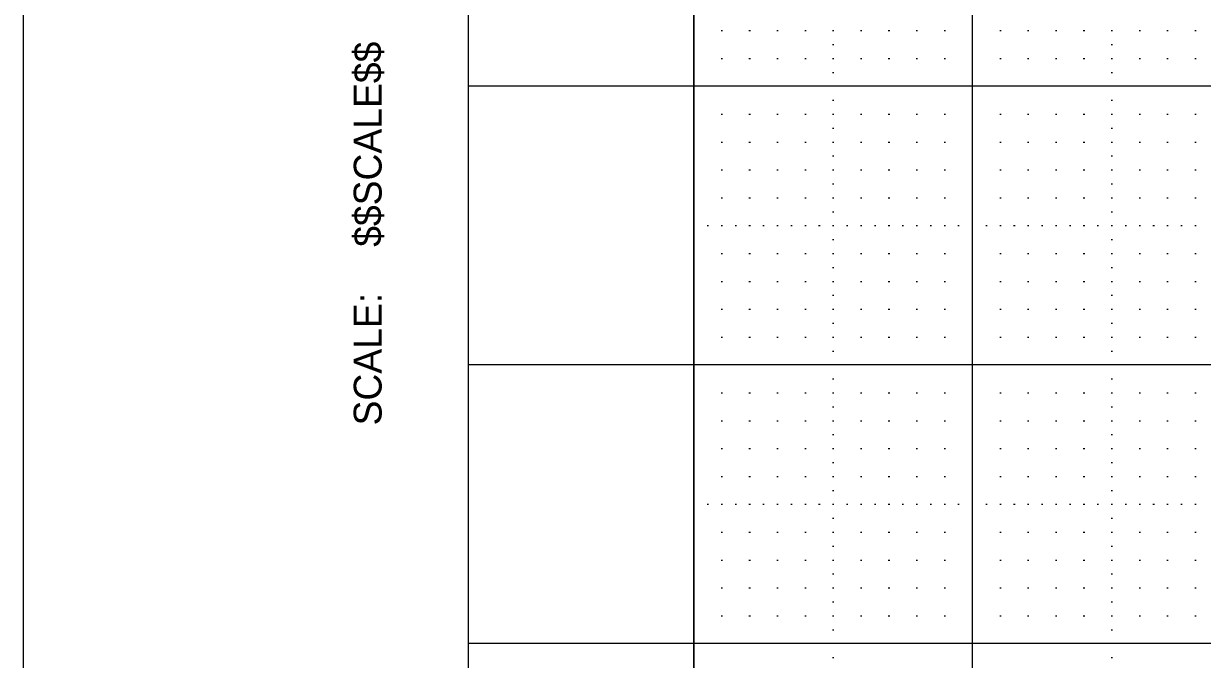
# Model space of a CAD drawing. Extents: x -1.6 to 32.4, y -1.9 to 21.6.
# Drawn here: x -1.598 to 2.633, y 2.488 to 4.77 of the extents above; entities that cross this region are included whole.
import ezdxf

# ---------------------------------------------------------------- set-up
doc = ezdxf.new("R2010")
doc.units = 0
for name, color, linetype in [('Level 1', 7, 'Continuous'), ('Level 4', 7, 'Continuous'), ('Level 5', 7, 'Continuous'), ('Level 61', 7, 'Continuous'), ('Level 63', 7, 'Continuous')]:
    doc.layers.add(name, color=color, linetype=linetype)

msp = doc.modelspace()

# ---------------------------------------------------------------- linework, layer by layer
at = {"layer": 'Level 1'}
msp.add_line((-0.001, -0.001), (-0.001, 20.545), dxfattribs=at)
at = {"layer": 'Level 4'}
for p, q in [((0.808, 0.545), (0.808, 20.545)), ((1.808, 0.545), (1.808, 20.545)), ((31.617, 4.545), (-0.001, 4.545)), ((31.617, 3.545), (-0.001, 3.545)), ((31.617, 2.545), (-0.001, 2.545))]:
    msp.add_line(p, q, dxfattribs=at)
at = {"layer": 'Level 5'}
for p, q in [((0.9055, 4.745), (0.9105, 4.745)), ((1.0055, 4.745), (1.0105, 4.745)), ((1.1055, 4.745), (1.1105, 4.745)), ((1.2055, 4.745), (1.2105, 4.745)), ((1.3055, 4.745), (1.3105, 4.745)), ((1.4055, 4.745), (1.4105, 4.745)), ((1.5055, 4.745), (1.5105, 4.745)), ((1.6055, 4.745), (1.6105, 4.745)), ((1.7055, 4.745), (1.7105, 4.745)), ((1.9055, 4.745), (1.9105, 4.745)), ((2.0055, 4.745), (2.0105, 4.745)), ((2.1055, 4.745), (2.1105, 4.745)), ((2.2055, 4.745), (2.2105, 4.745)), ((2.3055, 4.745), (2.3105, 4.745)), ((2.4055, 4.745), (2.4105, 4.745)), ((2.5055, 4.745), (2.5105, 4.745)), ((2.6055, 4.745), (2.6105, 4.745)), ((1.3055, 4.695), (1.3105, 4.695)), ((2.3055, 4.695), (2.3105, 4.695)), ((0.9055, 4.645), (0.9105, 4.645)), ((1.0055, 4.645), (1.0105, 4.645)), ((1.1055, 4.645), (1.1105, 4.645)), ((1.2055, 4.645), (1.2105, 4.645)), ((1.3055, 4.645), (1.3105, 4.645)), ((1.4055, 4.645), (1.4105, 4.645)), ((1.5055, 4.645), (1.5105, 4.645)), ((1.6055, 4.645), (1.6105, 4.645)), ((1.7055, 4.645), (1.7105, 4.645)), ((1.9055, 4.645), (1.9105, 4.645)), ((2.0055, 4.645), (2.0105, 4.645)), ((2.1055, 4.645), (2.1105, 4.645)), ((2.2055, 4.645), (2.2105, 4.645)), ((2.3055, 4.645), (2.3105, 4.645)), ((2.4055, 4.645), (2.4105, 4.645)), ((2.5055, 4.645), (2.5105, 4.645)), ((2.6055, 4.645), (2.6105, 4.645)), ((1.3055, 4.595), (1.3105, 4.595)), ((2.3055, 4.595), (2.3105, 4.595)), ((1.3055, 4.495), (1.3105, 4.495)), ((2.3055, 4.495), (2.3105, 4.495)), ((0.9055, 4.445), (0.9105, 4.445)), ((1.0055, 4.445), (1.0105, 4.445)), ((1.1055, 4.445), (1.1105, 4.445)), ((1.2055, 4.445), (1.2105, 4.445)), ((1.3055, 4.445), (1.3105, 4.445)), ((1.4055, 4.445), (1.4105, 4.445)), ((1.5055, 4.445), (1.5105, 4.445)), ((1.6055, 4.445), (1.6105, 4.445)), ((1.7055, 4.445), (1.7105, 4.445)), ((1.9055, 4.445), (1.9105, 4.445)), ((2.0055, 4.445), (2.0105, 4.445)), ((2.1055, 4.445), (2.1105, 4.445)), ((2.2055, 4.445), (2.2105, 4.445)), ((2.3055, 4.445), (2.3105, 4.445)), ((2.4055, 4.445), (2.4105, 4.445)), ((2.5055, 4.445), (2.5105, 4.445)), ((2.6055, 4.445), (2.6105, 4.445)), ((1.3055, 4.395), (1.3105, 4.395)), ((2.3055, 4.395), (2.3105, 4.395)), ((0.9055, 4.345), (0.9105, 4.345)), ((1.0055, 4.345), (1.0105, 4.345)), ((1.1055, 4.345), (1.1105, 4.345)), ((1.2055, 4.345), (1.2105, 4.345)), ((1.3055, 4.345), (1.3105, 4.345)), ((1.4055, 4.345), (1.4105, 4.345)), ((1.5055, 4.345), (1.5105, 4.345)), ((1.6055, 4.345), (1.6105, 4.345)), ((1.7055, 4.345), (1.7105, 4.345)), ((1.9055, 4.345), (1.9105, 4.345)), ((2.0055, 4.345), (2.0105, 4.345)), ((2.1055, 4.345), (2.1105, 4.345)), ((2.2055, 4.345), (2.2105, 4.345)), ((2.3055, 4.345), (2.3105, 4.345)), ((2.4055, 4.345), (2.4105, 4.345)), ((2.5055, 4.345), (2.5105, 4.345)), ((2.6055, 4.345), (2.6105, 4.345)), ((1.3055, 4.295), (1.3105, 4.295)), ((2.3055, 4.295), (2.3105, 4.295)), ((0.9055, 4.245), (0.9105, 4.245)), ((1.0055, 4.245), (1.0105, 4.245)), ((1.1055, 4.245), (1.1105, 4.245)), ((1.2055, 4.245), (1.2105, 4.245)), ((1.3055, 4.245), (1.3105, 4.245)), ((1.4055, 4.245), (1.4105, 4.245)), ((1.5055, 4.245), (1.5105, 4.245)), ((1.6055, 4.245), (1.6105, 4.245)), ((1.7055, 4.245), (1.7105, 4.245)), ((1.9055, 4.245), (1.9105, 4.245)), ((2.0055, 4.245), (2.0105, 4.245)), ((2.1055, 4.245), (2.1105, 4.245)), ((2.2055, 4.245), (2.2105, 4.245)), ((2.3055, 4.245), (2.3105, 4.245)), ((2.4055, 4.245), (2.4105, 4.245)), ((2.5055, 4.245), (2.5105, 4.245)), ((2.6055, 4.245), (2.6105, 4.245)), ((1.3055, 4.195), (1.3105, 4.195)), ((2.3055, 4.195), (2.3105, 4.195)), ((0.9055, 4.145), (0.9105, 4.145)), ((1.0055, 4.145), (1.0105, 4.145)), ((1.1055, 4.145), (1.1105, 4.145)), ((1.2055, 4.145), (1.2105, 4.145)), ((1.3055, 4.145), (1.3105, 4.145)), ((1.4055, 4.145), (1.4105, 4.145)), ((1.5055, 4.145), (1.5105, 4.145)), ((1.6055, 4.145), (1.6105, 4.145)), ((1.7055, 4.145), (1.7105, 4.145)), ((1.9055, 4.145), (1.9105, 4.145)), ((2.0055, 4.145), (2.0105, 4.145)), ((2.1055, 4.145), (2.1105, 4.145)), ((2.2055, 4.145), (2.2105, 4.145)), ((2.3055, 4.145), (2.3105, 4.145)), ((2.4055, 4.145), (2.4105, 4.145)), ((2.5055, 4.145), (2.5105, 4.145)), ((2.6055, 4.145), (2.6105, 4.145)), ((1.3055, 4.095), (1.3105, 4.095)), ((2.3055, 4.095), (2.3105, 4.095)), ((0.8555, 4.045), (0.8605, 4.045)), ((0.9055, 4.045), (0.9105, 4.045)), ((0.9555, 4.045), (0.9605, 4.045)), ((1.0055, 4.045), (1.0105, 4.045)), ((1.0555, 4.045), (1.0605, 4.045)), ((1.1055, 4.045), (1.1105, 4.045)), ((1.1555, 4.045), (1.1605, 4.045)), ((1.2055, 4.045), (1.2105, 4.045)), ((1.2555, 4.045), (1.2605, 4.045)), ((1.3055, 4.045), (1.3105, 4.045)), ((1.3555, 4.045), (1.3605, 4.045)), ((1.4055, 4.045), (1.4105, 4.045)), ((1.4555, 4.045), (1.4605, 4.045)), ((1.5055, 4.045), (1.5105, 4.045)), ((1.5555, 4.045), (1.5605, 4.045)), ((1.6055, 4.045), (1.6105, 4.045)), ((1.6555, 4.045), (1.6605, 4.045)), ((1.7055, 4.045), (1.7105, 4.045)), ((1.7555, 4.045), (1.7605, 4.045)), ((1.8555, 4.045), (1.8605, 4.045)), ((1.9055, 4.045), (1.9105, 4.045)), ((1.9555, 4.045), (1.9605, 4.045)), ((2.0055, 4.045), (2.0105, 4.045)), ((2.0555, 4.045), (2.0605, 4.045)), ((2.1055, 4.045), (2.1105, 4.045)), ((2.1555, 4.045), (2.1605, 4.045)), ((2.2055, 4.045), (2.2105, 4.045)), ((2.2555, 4.045), (2.2605, 4.045)), ((2.3055, 4.045), (2.3105, 4.045)), ((2.3555, 4.045), (2.3605, 4.045)), ((2.4055, 4.045), (2.4105, 4.045)), ((2.4555, 4.045), (2.4605, 4.045)), ((2.5055, 4.045), (2.5105, 4.045)), ((2.5555, 4.045), (2.5605, 4.045)), ((2.6055, 4.045), (2.6105, 4.045)), ((1.3055, 3.995), (1.3105, 3.995)), ((2.3055, 3.995), (2.3105, 3.995)), ((0.9055, 3.945), (0.9105, 3.945)), ((1.0055, 3.945), (1.0105, 3.945)), ((1.1055, 3.945), (1.1105, 3.945)), ((1.2055, 3.945), (1.2105, 3.945)), ((1.3055, 3.945), (1.3105, 3.945)), ((1.4055, 3.945), (1.4105, 3.945)), ((1.5055, 3.945), (1.5105, 3.945)), ((1.6055, 3.945), (1.6105, 3.945)), ((1.7055, 3.945), (1.7105, 3.945)), ((1.9055, 3.945), (1.9105, 3.945)), ((2.0055, 3.945), (2.0105, 3.945)), ((2.1055, 3.945), (2.1105, 3.945)), ((2.2055, 3.945), (2.2105, 3.945)), ((2.3055, 3.945), (2.3105, 3.945)), ((2.4055, 3.945), (2.4105, 3.945)), ((2.5055, 3.945), (2.5105, 3.945)), ((2.6055, 3.945), (2.6105, 3.945)), ((1.3055, 3.895), (1.3105, 3.895)), ((2.3055, 3.895), (2.3105, 3.895)), ((0.9055, 3.845), (0.9105, 3.845)), ((1.0055, 3.845), (1.0105, 3.845)), ((1.1055, 3.845), (1.1105, 3.845)), ((1.2055, 3.845), (1.2105, 3.845)), ((1.3055, 3.845), (1.3105, 3.845)), ((1.4055, 3.845), (1.4105, 3.845)), ((1.5055, 3.845), (1.5105, 3.845)), ((1.6055, 3.845), (1.6105, 3.845)), ((1.7055, 3.845), (1.7105, 3.845)), ((1.9055, 3.845), (1.9105, 3.845)), ((2.0055, 3.845), (2.0105, 3.845)), ((2.1055, 3.845), (2.1105, 3.845)), ((2.2055, 3.845), (2.2105, 3.845)), ((2.3055, 3.845), (2.3105, 3.845)), ((2.4055, 3.845), (2.4105, 3.845)), ((2.5055, 3.845), (2.5105, 3.845)), ((2.6055, 3.845), (2.6105, 3.845)), ((1.3055, 3.795), (1.3105, 3.795)), ((2.3055, 3.795), (2.3105, 3.795)), ((0.9055, 3.745), (0.9105, 3.745)), ((1.0055, 3.745), (1.0105, 3.745)), ((1.1055, 3.745), (1.1105, 3.745)), ((1.2055, 3.745), (1.2105, 3.745)), ((1.3055, 3.745), (1.3105, 3.745)), ((1.4055, 3.745), (1.4105, 3.745)), ((1.5055, 3.745), (1.5105, 3.745)), ((1.6055, 3.745), (1.6105, 3.745)), ((1.7055, 3.745), (1.7105, 3.745)), ((1.9055, 3.745), (1.9105, 3.745)), ((2.0055, 3.745), (2.0105, 3.745)), ((2.1055, 3.745), (2.1105, 3.745)), ((2.2055, 3.745), (2.2105, 3.745)), ((2.3055, 3.745), (2.3105, 3.745)), ((2.4055, 3.745), (2.4105, 3.745)), ((2.5055, 3.745), (2.5105, 3.745)), ((2.6055, 3.745), (2.6105, 3.745)), ((1.3055, 3.695), (1.3105, 3.695)), ((2.3055, 3.695), (2.3105, 3.695)), ((0.9055, 3.645), (0.9105, 3.645)), ((1.0055, 3.645), (1.0105, 3.645)), ((1.1055, 3.645), (1.1105, 3.645)), ((1.2055, 3.645), (1.2105, 3.645)), ((1.3055, 3.645), (1.3105, 3.645)), ((1.4055, 3.645), (1.4105, 3.645)), ((1.5055, 3.645), (1.5105, 3.645)), ((1.6055, 3.645), (1.6105, 3.645)), ((1.7055, 3.645), (1.7105, 3.645)), ((1.9055, 3.645), (1.9105, 3.645)), ((2.0055, 3.645), (2.0105, 3.645)), ((2.1055, 3.645), (2.1105, 3.645)), ((2.2055, 3.645), (2.2105, 3.645)), ((2.3055, 3.645), (2.3105, 3.645)), ((2.4055, 3.645), (2.4105, 3.645)), ((2.5055, 3.645), (2.5105, 3.645)), ((2.6055, 3.645), (2.6105, 3.645)), ((1.3055, 3.595), (1.3105, 3.595)), ((2.3055, 3.595), (2.3105, 3.595)), ((1.3055, 3.495), (1.3105, 3.495)), ((2.3055, 3.495), (2.3105, 3.495)), ((0.9055, 3.445), (0.9105, 3.445)), ((1.0055, 3.445), (1.0105, 3.445)), ((1.1055, 3.445), (1.1105, 3.445)), ((1.2055, 3.445), (1.2105, 3.445)), ((1.3055, 3.445), (1.3105, 3.445)), ((1.4055, 3.445), (1.4105, 3.445)), ((1.5055, 3.445), (1.5105, 3.445)), ((1.6055, 3.445), (1.6105, 3.445)), ((1.7055, 3.445), (1.7105, 3.445)), ((1.9055, 3.445), (1.9105, 3.445)), ((2.0055, 3.445), (2.0105, 3.445)), ((2.1055, 3.445), (2.1105, 3.445)), ((2.2055, 3.445), (2.2105, 3.445)), ((2.3055, 3.445), (2.3105, 3.445)), ((2.4055, 3.445), (2.4105, 3.445)), ((2.5055, 3.445), (2.5105, 3.445)), ((2.6055, 3.445), (2.6105, 3.445)), ((1.3055, 3.395), (1.3105, 3.395)), ((2.3055, 3.395), (2.3105, 3.395)), ((0.9055, 3.345), (0.9105, 3.345)), ((1.0055, 3.345), (1.0105, 3.345)), ((1.1055, 3.345), (1.1105, 3.345)), ((1.2055, 3.345), (1.2105, 3.345)), ((1.3055, 3.345), (1.3105, 3.345)), ((1.4055, 3.345), (1.4105, 3.345)), ((1.5055, 3.345), (1.5105, 3.345)), ((1.6055, 3.345), (1.6105, 3.345)), ((1.7055, 3.345), (1.7105, 3.345)), ((1.9055, 3.345), (1.9105, 3.345)), ((2.0055, 3.345), (2.0105, 3.345)), ((2.1055, 3.345), (2.1105, 3.345)), ((2.2055, 3.345), (2.2105, 3.345)), ((2.3055, 3.345), (2.3105, 3.345)), ((2.4055, 3.345), (2.4105, 3.345)), ((2.5055, 3.345), (2.5105, 3.345)), ((2.6055, 3.345), (2.6105, 3.345)), ((1.3055, 3.295), (1.3105, 3.295)), ((2.3055, 3.295), (2.3105, 3.295)), ((0.9055, 3.245), (0.9105, 3.245)), ((1.0055, 3.245), (1.0105, 3.245)), ((1.1055, 3.245), (1.1105, 3.245)), ((1.2055, 3.245), (1.2105, 3.245)), ((1.3055, 3.245), (1.3105, 3.245)), ((1.4055, 3.245), (1.4105, 3.245)), ((1.5055, 3.245), (1.5105, 3.245)), ((1.6055, 3.245), (1.6105, 3.245)), ((1.7055, 3.245), (1.7105, 3.245)), ((1.9055, 3.245), (1.9105, 3.245)), ((2.0055, 3.245), (2.0105, 3.245)), ((2.1055, 3.245), (2.1105, 3.245)), ((2.2055, 3.245), (2.2105, 3.245)), ((2.3055, 3.245), (2.3105, 3.245)), ((2.4055, 3.245), (2.4105, 3.245)), ((2.5055, 3.245), (2.5105, 3.245)), ((2.6055, 3.245), (2.6105, 3.245)), ((1.3055, 3.195), (1.3105, 3.195)), ((2.3055, 3.195), (2.3105, 3.195)), ((0.9055, 3.145), (0.9105, 3.145)), ((1.0055, 3.145), (1.0105, 3.145)), ((1.1055, 3.145), (1.1105, 3.145)), ((1.2055, 3.145), (1.2105, 3.145)), ((1.3055, 3.145), (1.3105, 3.145)), ((1.4055, 3.145), (1.4105, 3.145)), ((1.5055, 3.145), (1.5105, 3.145)), ((1.6055, 3.145), (1.6105, 3.145)), ((1.7055, 3.145), (1.7105, 3.145)), ((1.9055, 3.145), (1.9105, 3.145)), ((2.0055, 3.145), (2.0105, 3.145)), ((2.1055, 3.145), (2.1105, 3.145)), ((2.2055, 3.145), (2.2105, 3.145)), ((2.3055, 3.145), (2.3105, 3.145)), ((2.4055, 3.145), (2.4105, 3.145)), ((2.5055, 3.145), (2.5105, 3.145)), ((2.6055, 3.145), (2.6105, 3.145)), ((1.3055, 3.095), (1.3105, 3.095)), ((2.3055, 3.095), (2.3105, 3.095)), ((0.8555, 3.045), (0.8605, 3.045)), ((0.9055, 3.045), (0.9105, 3.045)), ((0.9555, 3.045), (0.9605, 3.045)), ((1.0055, 3.045), (1.0105, 3.045)), ((1.0555, 3.045), (1.0605, 3.045)), ((1.1055, 3.045), (1.1105, 3.045)), ((1.1555, 3.045), (1.1605, 3.045)), ((1.2055, 3.045), (1.2105, 3.045)), ((1.2555, 3.045), (1.2605, 3.045)), ((1.3055, 3.045), (1.3105, 3.045)), ((1.3555, 3.045), (1.3605, 3.045)), ((1.4055, 3.045), (1.4105, 3.045)), ((1.4555, 3.045), (1.4605, 3.045)), ((1.5055, 3.045), (1.5105, 3.045)), ((1.5555, 3.045), (1.5605, 3.045)), ((1.6055, 3.045), (1.6105, 3.045)), ((1.6555, 3.045), (1.6605, 3.045)), ((1.7055, 3.045), (1.7105, 3.045)), ((1.7555, 3.045), (1.7605, 3.045)), ((1.8555, 3.045), (1.8605, 3.045)), ((1.9055, 3.045), (1.9105, 3.045)), ((1.9555, 3.045), (1.9605, 3.045)), ((2.0055, 3.045), (2.0105, 3.045)), ((2.0555, 3.045), (2.0605, 3.045)), ((2.1055, 3.045), (2.1105, 3.045)), ((2.1555, 3.045), (2.1605, 3.045)), ((2.2055, 3.045), (2.2105, 3.045)), ((2.2555, 3.045), (2.2605, 3.045)), ((2.3055, 3.045), (2.3105, 3.045)), ((2.3555, 3.045), (2.3605, 3.045)), ((2.4055, 3.045), (2.4105, 3.045)), ((2.4555, 3.045), (2.4605, 3.045)), ((2.5055, 3.045), (2.5105, 3.045)), ((2.5555, 3.045), (2.5605, 3.045)), ((2.6055, 3.045), (2.6105, 3.045)), ((1.3055, 2.995), (1.3105, 2.995)), ((2.3055, 2.995), (2.3105, 2.995)), ((0.9055, 2.945), (0.9105, 2.945)), ((1.0055, 2.945), (1.0105, 2.945)), ((1.1055, 2.945), (1.1105, 2.945)), ((1.2055, 2.945), (1.2105, 2.945)), ((1.3055, 2.945), (1.3105, 2.945)), ((1.4055, 2.945), (1.4105, 2.945)), ((1.5055, 2.945), (1.5105, 2.945)), ((1.6055, 2.945), (1.6105, 2.945)), ((1.7055, 2.945), (1.7105, 2.945)), ((1.9055, 2.945), (1.9105, 2.945)), ((2.0055, 2.945), (2.0105, 2.945)), ((2.1055, 2.945), (2.1105, 2.945)), ((2.2055, 2.945), (2.2105, 2.945)), ((2.3055, 2.945), (2.3105, 2.945)), ((2.4055, 2.945), (2.4105, 2.945)), ((2.5055, 2.945), (2.5105, 2.945)), ((2.6055, 2.945), (2.6105, 2.945)), ((1.3055, 2.895), (1.3105, 2.895)), ((2.3055, 2.895), (2.3105, 2.895)), ((0.9055, 2.845), (0.9105, 2.845)), ((1.0055, 2.845), (1.0105, 2.845)), ((1.1055, 2.845), (1.1105, 2.845)), ((1.2055, 2.845), (1.2105, 2.845)), ((1.3055, 2.845), (1.3105, 2.845)), ((1.4055, 2.845), (1.4105, 2.845)), ((1.5055, 2.845), (1.5105, 2.845)), ((1.6055, 2.845), (1.6105, 2.845)), ((1.7055, 2.845), (1.7105, 2.845)), ((1.9055, 2.845), (1.9105, 2.845)), ((2.0055, 2.845), (2.0105, 2.845)), ((2.1055, 2.845), (2.1105, 2.845)), ((2.2055, 2.845), (2.2105, 2.845)), ((2.3055, 2.845), (2.3105, 2.845)), ((2.4055, 2.845), (2.4105, 2.845)), ((2.5055, 2.845), (2.5105, 2.845)), ((2.6055, 2.845), (2.6105, 2.845)), ((1.3055, 2.795), (1.3105, 2.795)), ((2.3055, 2.795), (2.3105, 2.795)), ((0.9055, 2.745), (0.9105, 2.745)), ((1.0055, 2.745), (1.0105, 2.745)), ((1.1055, 2.745), (1.1105, 2.745)), ((1.2055, 2.745), (1.2105, 2.745)), ((1.3055, 2.745), (1.3105, 2.745)), ((1.4055, 2.745), (1.4105, 2.745)), ((1.5055, 2.745), (1.5105, 2.745)), ((1.6055, 2.745), (1.6105, 2.745)), ((1.7055, 2.745), (1.7105, 2.745)), ((1.9055, 2.745), (1.9105, 2.745)), ((2.0055, 2.745), (2.0105, 2.745)), ((2.1055, 2.745), (2.1105, 2.745)), ((2.2055, 2.745), (2.2105, 2.745)), ((2.3055, 2.745), (2.3105, 2.745)), ((2.4055, 2.745), (2.4105, 2.745)), ((2.5055, 2.745), (2.5105, 2.745)), ((2.6055, 2.745), (2.6105, 2.745)), ((1.3055, 2.695), (1.3105, 2.695)), ((2.3055, 2.695), (2.3105, 2.695)), ((0.9055, 2.645), (0.9105, 2.645)), ((1.0055, 2.645), (1.0105, 2.645)), ((1.1055, 2.645), (1.1105, 2.645)), ((1.2055, 2.645), (1.2105, 2.645)), ((1.3055, 2.645), (1.3105, 2.645)), ((1.4055, 2.645), (1.4105, 2.645)), ((1.5055, 2.645), (1.5105, 2.645)), ((1.6055, 2.645), (1.6105, 2.645)), ((1.7055, 2.645), (1.7105, 2.645)), ((1.9055, 2.645), (1.9105, 2.645)), ((2.0055, 2.645), (2.0105, 2.645)), ((2.1055, 2.645), (2.1105, 2.645)), ((2.2055, 2.645), (2.2105, 2.645)), ((2.3055, 2.645), (2.3105, 2.645)), ((2.4055, 2.645), (2.4105, 2.645)), ((2.5055, 2.645), (2.5105, 2.645)), ((2.6055, 2.645), (2.6105, 2.645)), ((1.3055, 2.595), (1.3105, 2.595)), ((2.3055, 2.595), (2.3105, 2.595)), ((1.3055, 2.495), (1.3105, 2.495)), ((2.3055, 2.495), (2.3105, 2.495))]:
    msp.add_line(p, q, dxfattribs=at)
at = {"layer": 'Level 61'}
msp.add_lwpolyline([(0.808, 0.545), (30.808, 0.545), (30.8079, 19.7222), (26.3984, 19.7217), (26.3984, 19.7217), (26.3984, 19.7217), (26.3984, 19.7217), (26.3984, 19.7217), (26.3984, 20.545), (26.3984, 20.545), (26.3984, 20.545), (0.808, 20.545)], close=True, dxfattribs=at)
at = {"layer": 'Level 63'}
msp.add_lwpolyline([(-1.598, 21.273), (32.402, 21.273), (32.402, -0.727), (-1.598, -0.727)], close=True, dxfattribs=at)

# ---------------------------------------------------------------- texts
at = {"layer": 'Level 1'}
for s, p in [('$$SCALE$$', (-0.313, 3.969)), ('SCALE:', (-0.313, 3.328))]:
    msp.add_text(s, height=0.1, rotation=90, dxfattribs=at).set_placement(p)

doc.saveas('drawing.dxf')
